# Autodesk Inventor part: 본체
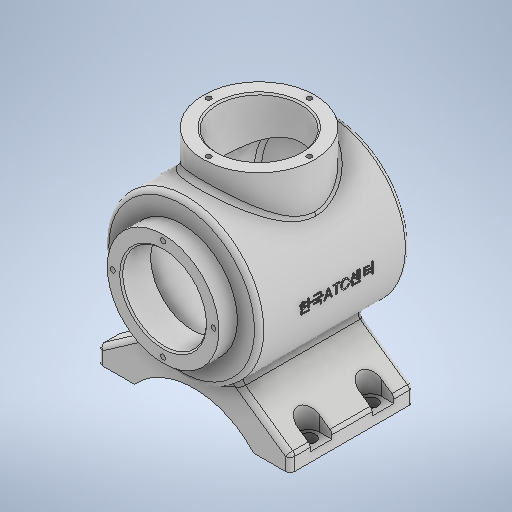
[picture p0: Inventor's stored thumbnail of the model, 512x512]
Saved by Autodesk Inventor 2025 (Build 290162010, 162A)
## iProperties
Created: 2024-07
Part Number: 본체
Material: 일반
Document SubType Name: Modeling
Designer: 학생
Density: 1 g/cm^3
Appearance: 기본값
Author: 학생
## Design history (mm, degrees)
sketch "스케치2"
  geometry: C1 r 50 at (0, 0); 1 further point
  constraints: 1 centre point, 1 coincident
  dimensions: "d2" = 100 diameter of C1
extrude "돌출1" new body sketch "스케치2" stored distance "d3" = 108; taper "d4" = 0 deg
sketch "스케치3"
  geometry: L1 (-50, -54)-(50, -54) reference; L2 (-50, -54)-(-50, 54) reference; L3 (50, -54)-(50, 54) reference; L4 (0, 101.157)-(0, -90.836); A1 r 113 centre (0, 59) between (-50, -42.336) and (50, -42.336); 2 further points
  constraints: 3 point on line, 2 end point, 2 point on circle, 1 centre point, 1 tangent, 1 vertical, 1 vertical alignment
  dimensions: "d5" = 113 radius of A1
revolve "회전1" sketch "스케치3" stored, may be unused: angle "d6" = 90 deg
fillet "모깎기1" dims "d7" = 3
feature "쉘1" dims "d8" = 7
sketch "스케치4"
  geometry: C1 r 36 at (0, 0); 1 further point
  constraints: 1 centre point, 1 coincident
  dimensions: "d9" = 72 diameter of C1
extrude "돌출2" join sketch "스케치4" distance "d10" = 12; taper "d11" = 0 deg
sketch "스케치5"
  geometry: C1 r 36 at (0, 0) reference; 2 further points
  constraints: 1 coincident
hole "구멍1" sketch "스케치5" at (0, 0) diameter "d12" = 54; stored, may be unused: countersink angle "d16" = 90 deg, drill point angle "d18" = 0 deg; dims "d13" = 8, "d14" = 4, "d15" = 2, "d17" = 19
fillet "모깎기2" dims "d19" = 3
fillet "모깎기3" dims "d20" = 3
chamfer "모따기1" distance "d21" = 1; stored, may be unused: second distance "d22" = 2, angle "d23" = 45 deg
sketch "스케치6"
  geometry: L1 (-62, -77)-(62, -77); L2 (-62, -77)-(-62, -67); L3 (-62, -67)-(-26.694, -42.278); L4 (62, -77)-(62, -67); L5 (62, -67)-(26.694, -42.278); L6 (0, 62.14)-(0, -91.323); A1 r 50 centre (0, 0) between (-26.694, -42.278) and (26.694, -42.278) reference; A2 r 52.096 centre (0, -112.096) between (38.5, -77) and (-38.5, -77); 4 further points
  constraints: 12 end point, 5 point on circle, 3 point on line, 3 vertical, 2 equal length, 2 midpoint, 1 centre point, 1 horizontal, 1 vertical alignment, 1 other
  dimensions: "d24" = 10 distance of L1.start L2.end; "d25" = 77 distance from line of point (0, 0) L1; "d26" = 55 deg angle of L4 L5; "d27" = 17 distance of point (0, -77) point (0, -60); "d28" = 77 distance of A2.start A2.end; "d29" = 124 distance from line of point (-62, -72) L4
extrude "돌출3" join sketch "스케치6" distance "d30" = 46; taper "d31" = 0 deg; dims "d32" = 34, "d33" = 0
fillet "모깎기4" dims "d34" = 3
fillet "모깎기5" dims "d35" = 3
fillet "모깎기6" dims "d36" = 3
node "작업 평면1"
sketch "스케치7"
  geometry: L1 (-2.5, 100)-(-74.5, 100) reference; C1 r 36 at (-38.5, 38); 1 further point
  constraints: 1 centre point, 1 vertical alignment
  dimensions: "d39" = 72 diameter of C1; "d40" = 62 distance from line of L1 C1.centre
extrude "돌출4" join sketch "스케치7" stored distance "d41" = 46; taper "d42" = 0 deg
sketch "스케치8"
  geometry: C1 r 36 at (0, 0) reference; 2 further points
  constraints: 1 coincident
hole "구멍2" sketch "스케치8" at (0, 0) diameter "d43" = 54; stored, may be unused: countersink angle "d47" = 90 deg, drill point angle "d49" = 0 deg; dims "d44" = 6, "d45" = 4, "d46" = 2, "d48" = 50
chamfer "모따기2" distance "d50" = 1; stored, may be unused: second distance "d51" = 2, angle "d52" = 45 deg
node "작업 평면2"
sketch "스케치9"
  geometry: L1 (23.5, 3)-(23.5, 77) reference; L2 (15.5, 27)-(23.5, 27); L3 (20.5, 0)-(0, 0) reference; L4 (15.5, 13)-(23.5, 13); L5 (-100.5, 77)-(-100.5, 3) reference; L6 (-100.5, 40)-(23.5, 40); L7 (-38.5, -15.146)-(-38.5, 101.944); L8 (15.5, 67)-(23.5, 67); L9 (15.5, 53)-(23.5, 53); L10 (-92.5, 13)-(-100.5, 13); L11 (-92.5, 27)-(-100.5, 27); L12 (-92.5, 53)-(-100.5, 53); L13 (-92.5, 67)-(-100.5, 67); A1 r 7 centre (15.5, 20) between (15.5, 27) and (15.5, 13); A2 r 7 centre (15.5, 60) between (15.5, 67) and (15.5, 53); A3 r 7 centre (-92.5, 20) between (-92.5, 13) and (-92.5, 27); A4 r 7 centre (-92.5, 60) between (-92.5, 53) and (-92.5, 67); 8 further points
  constraints: 20 end point, 15 symmetric about line, 8 point on circle, 4 centre point, 3 midpoint, 3 point on line, 1 horizontal, 1 perpendicular, 1 tangent, 1 vertical, 3 other
  dimensions: "d54" = 20 distance from line of L3 A1.centre; "d56" = 14 distance between parallel lines of L4 L2; "d57" = 8 distance from line of A1.centre L1; "d58" = 14 diameter of A1
extrude "돌출5" cut sketch "스케치9" stored distance "d59" = 10; taper "d60" = 0 deg
sketch "스케치10"
  geometry: A1 r 7 centre (15.5, -60) between (15.5, -53) and (15.5, -67) reference; A2 r 7 centre (15.5, -20) between (15.5, -13) and (15.5, -27) reference; A3 r 7 centre (-92.5, -60) between (-92.5, -67) and (-92.5, -53) reference; A4 r 7 centre (-92.5, -20) between (-92.5, -27) and (-92.5, -13) reference; 5 further points
  constraints: 4 coincident
hole "구멍3" sketch "스케치10" at (15.5, -60), (15.5, -20), (-92.5, -60), (-92.5, -20) diameter "d61" = 9; stored, may be unused: countersink angle "d65" = 90 deg, drill point angle "d67" = 0 deg; dims "d62" = 6, "d63" = 4, "d64" = 2, "d66" = 50
fillet "모깎기7" dims "d68" = 3
sketch "스케치11"
  geometry: C1 r 36 at (0, 0) reference; 2 further points
  constraints: 1 vertical alignment
  dimensions: "d69" = 32.5 distance of C1.centre point (0, 32.5)
hole "구멍4" sketch "스케치11" at (0, 32.5) diameter "d70" = 3.242; stored, may be unused: countersink angle "d74" = 90 deg, drill point angle "d76" = 120 deg; dims "d71" = 8, "d72" = 4, "d73" = 2, "d75" = 10
sketch "스케치12"
  geometry: 2 further points
  constraints: 1 vertical alignment
  dimensions: "d77" = 32.5 distance of point (0, 0) point (0, 32.5)
hole "구멍5" sketch "스케치12" at (0, 32.5) diameter "d78" = 3.242; stored, may be unused: countersink angle "d82" = 90 deg, drill point angle "d84" = 120 deg; dims "d79" = 8, "d80" = 4, "d81" = 2, "d83" = 10
node "작업 평면3"
sketch "스케치13"
  geometry: L1 (36, 66)-(-36, 66) reference; 2 further points
  constraints: 1 vertical alignment, 1 other
  dimensions: "d92" = 62 distance from line of L1 point (0, 4)
feature "엠보싱1" sketch "스케치13" dims "d8" = 7, "d93" = 0.5, "d94" = 0
node "솔리드1"
pattern_circular "원형 패턴1" dims angle "d86" = 360 deg
pattern_circular "원형 패턴2" dims angle "d89" = 360 deg
feature "A9D066F2-1C7D-4E18-AEED-F7BC21143FA4" dims "d12" = 54, "d13" = 8, "d14" = 4, "d15" = 2, "d16" = 90 deg, "d17" = 19, "d18" = 0
other parameters: "d37" = -142, "d53" = -6, "d91" = 124.25
